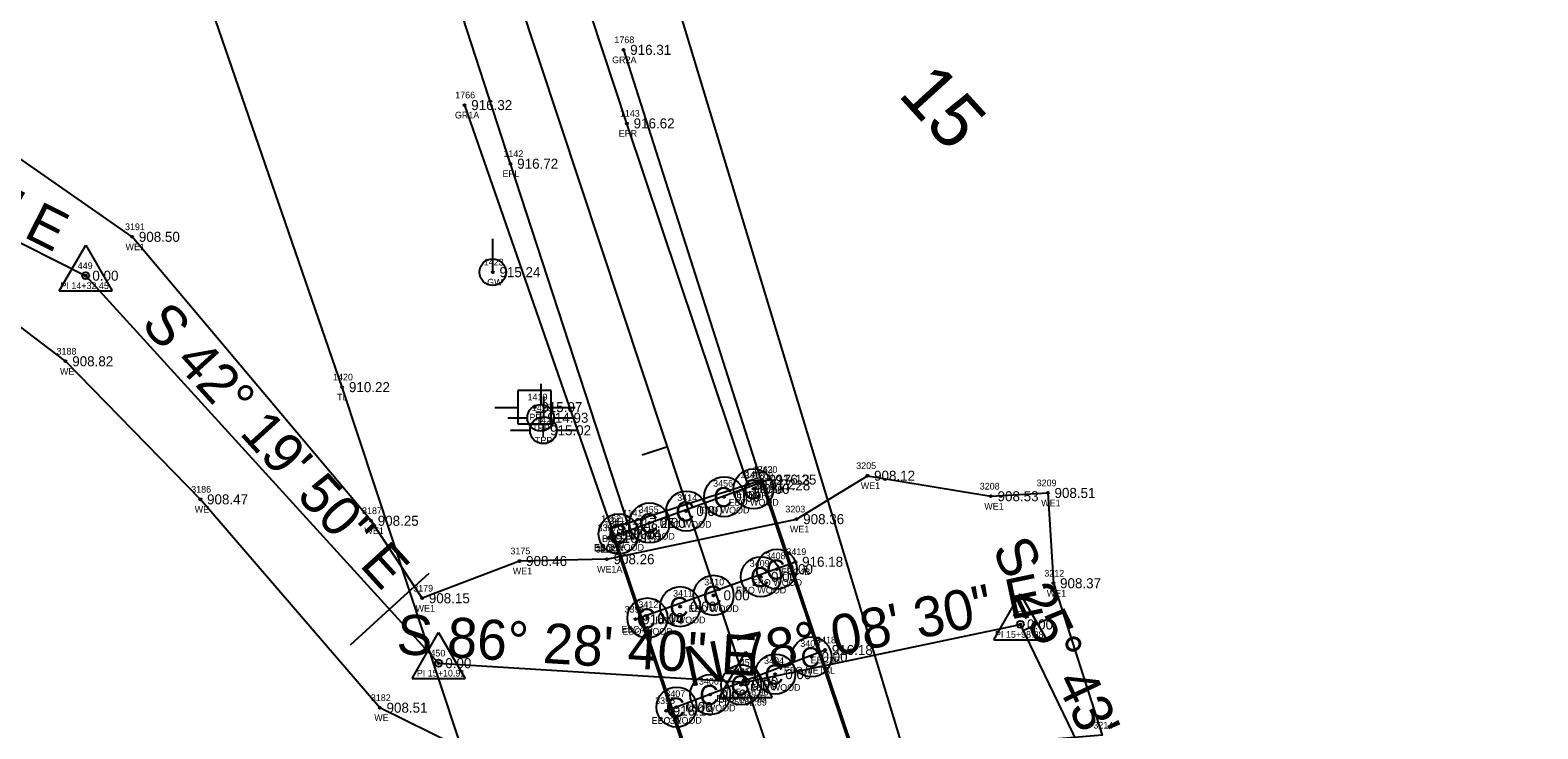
# Model space of a CAD drawing. Extents: x 1528109 to 1531398, y 1157799 to 1162548.
# Drawn here: x 1529420.7 to 1529646.4, y 1160628.8 to 1160733.4 of the extents above; entities that cross this region are included whole.
import ezdxf

# ---------------------------------------------------------------- set-up
doc = ezdxf.new("R2010")
doc.units = 0
for name, color, linetype in [('RD_EX_Bridge', 7, 'Continuous'), ('RD_EX_Bridge_txCode', 7, 'Continuous'), ('RD_EX_GuardRail', 7, 'Continuous'), ('RD_EX_GuardRail_txCode', 7, 'Continuous'), ('RD_EX_H2O', 7, 'Continuous'), ('RD_EX_H2O_txCode', 7, 'Continuous'), ('RD_EX_Road', 7, 'Continuous'), ('RD_EX_Road_txCode', 7, 'Continuous'), ('RD_EX_TX_Bridge_ELEV', 7, 'Continuous'), ('RD_EX_TX_GuardRail_ELEV', 7, 'Continuous'), ('RD_EX_TX_H2O_ELEV', 7, 'Continuous'), ('RD_EX_TX_Road_ELEV', 7, 'Continuous'), ('RD_EX_TX_UT_ELEV', 7, 'Continuous'), ('RD_EX_TX_VEG_ELEV', 7, 'Continuous'), ('RD_EX_UT', 7, 'Continuous'), ('RD_EX_UT_txCode', 7, 'Continuous'), ('RD_EX_VEG', 7, 'Continuous'), ('RD_EX_VEG_txCode', 7, 'Continuous'), ('RD_HC_Cl', 7, 'Continuous'), ('RD_HC_Data', 7, 'Continuous'), ('RD_HC_Data_Tic', 7, 'Continuous'), ('RD_HC_Survey_ELEV', 7, 'Continuous'), ('RD_HC_TX_Sta50', 7, 'Continuous'), ('RD_HC_txCode', 7, 'Continuous'), ('RD_SMD_Locator', 7, 'Continuous')]:
    doc.layers.add(name, color=color, linetype=linetype)

msp = doc.modelspace()

# ---------------------------------------------------------------- linework, layer by layer
at = {"layer": 'RD_EX_Bridge'}
for p, q in [((1529507.33, 1160657.36), (1529531.31, 1160666.08)), ((1529511.38, 1160645.17), (1529535.31, 1160653.78)), ((1529515.94, 1160631.48), (1529539.75, 1160640.57))]:
    msp.add_line(p, q, dxfattribs=at)
msp.add_lwpolyline([(1529525.42, 1160605.53), (1529507.61, 1160658.74), (1529530.31, 1160666.05), (1529548.07, 1160613.22), (1529525.42, 1160605.53)], dxfattribs=at)
for centre in [(1529529.03, 1160664.68), (1529524.64, 1160663.51), (1529513.48, 1160659.6), (1529518.97, 1160661.37), (1529508.85, 1160657.95), (1529530.14, 1160651.53), (1529532.52, 1160652.67), (1529523.05, 1160648.75), (1529518.05, 1160647.06), (1529513.15, 1160645.36), (1529537.71, 1160639.54), (1529532.29, 1160636.96), (1529527.19, 1160635.34), (1529522.55, 1160633.89), (1529517.51, 1160632.03)]:
    msp.add_circle(centre, 3, dxfattribs=at)
at = {"layer": 'RD_EX_GuardRail'}
for points in [[(1529509.58, 1160730.41), (1529530.39, 1160665.21), (1529547.6, 1160613.9), (1529568.73, 1160551.39)], [(1529485.78, 1160722.14), (1529508.08, 1160657.89), (1529525.55, 1160605.96), (1529546.28, 1160543.06)]]:
    msp.add_lwpolyline(points, dxfattribs=at)
at = {"layer": 'RD_EX_H2O'}
for points in [[(1529507.08, 1160654.16), (1529493.99, 1160653.89), (1529479.43, 1160648.32), (1529471.78, 1160659.91), (1529436.02, 1160702.42), (1529412.59, 1160718.71), (1529383.74, 1160723.99), (1529372.31, 1160730.96)], [(1529521, 1160615.38), (1529503.83, 1160616.75), (1529473.1, 1160631.93), (1529446.23, 1160663.12), (1529426.05, 1160683.79), (1529383.42, 1160716.17), (1529369.51, 1160721.6)], [(1529507.08, 1160654.16), (1529535.47, 1160660.16), (1529546.08, 1160666.66), (1529564.57, 1160663.59), (1529573.09, 1160664.08), (1529573.92, 1160650.56), (1529581.25, 1160627.81), (1529566.4, 1160626.59), (1529547.24, 1160619.32), (1529521, 1160615.38)]]:
    msp.add_lwpolyline(points, dxfattribs=at)
at = {"layer": 'RD_EX_Road'}
for points in [[(1529528.19, 1160665.37), (1529510.09, 1160719.4), (1529492.11, 1160773.83), (1529472.86, 1160831.89), (1529455.25, 1160885.7), (1529433.06, 1160953.02), (1529413.26, 1161012.66), (1529395.22, 1161066.33), (1529377.86, 1161117.62), (1529363.16, 1161161.33), (1529348.16, 1161206.56), (1529333.57, 1161252.24), (1529320.05, 1161297.19), (1529307.5, 1161343.12), (1529295.36, 1161392.47), (1529283.79, 1161439.12), (1529272.62, 1161487.93), (1529262.64, 1161533.9), (1529252.45, 1161583.34), (1529240.63, 1161641.16), (1529229.5, 1161693.86), (1529218.57, 1161746.16)], [(1529510.2, 1160659.58), (1529492.66, 1160713.36), (1529475.03, 1160767.61), (1529455.71, 1160825.55), (1529437.49, 1160880.26), (1529415.33, 1160947.23), (1529395.75, 1161006.55), (1529377.65, 1161060.34), (1529360.29, 1161111.94), (1529345.55, 1161156.09), (1529330.61, 1161201.56), (1529315.83, 1161247.44), (1529302.44, 1161292.45), (1529289.17, 1161338.91), (1529275.89, 1161388.06), (1529264.25, 1161434.63), (1529253.41, 1161483.36), (1529243.45, 1161529.92), (1529233.03, 1161578.98), (1529220.82, 1161638.04), (1529209.58, 1161691.45), (1529199.11, 1161741.7)]]:
    msp.add_lwpolyline(points, dxfattribs=at)
at = {"layer": 'RD_EX_UT'}
for p, q in [((1529490, 1160697.13), (1529490, 1160702.13)), ((1529498.76, 1160679.44), (1529493.76, 1160679.44)), ((1529493.76, 1160679.44), (1529493.76, 1160674.44)), ((1529497.18, 1160680.4), (1529497.18, 1160677.33)), ((1529497.58, 1160678.53), (1529497.58, 1160675.46)), ((1529498.76, 1160674.44), (1529498.76, 1160679.44)), ((1529490.33, 1160676.88), (1529493.8, 1160676.88)), ((1529498.69, 1160676.88), (1529502.33, 1160676.88)), ((1529492.25, 1160675.34), (1529495.18, 1160675.34)), ((1529493.76, 1160674.44), (1529498.76, 1160674.44)), ((1529499.18, 1160675.34), (1529502.25, 1160675.34)), ((1529492.65, 1160673.48), (1529495.58, 1160673.48)), ((1529499.58, 1160673.48), (1529502.65, 1160673.48))]:
    msp.add_line(p, q, dxfattribs=at)
for centre in [(1529490, 1160697.13), (1529497.18, 1160675.33), (1529497.58, 1160673.46)]:
    msp.add_circle(centre, 2, dxfattribs=at)
at = {"layer": 'RD_EX_VEG'}
for points in [[(1529712.92, 1160313.49), (1529665.06, 1160326.09), (1529626.42, 1160407.72), (1529580.03, 1160531.48), (1529510.74, 1160760.21), (1529455.97, 1160902.21), (1529420.7, 1161006.64), (1529376.36, 1161143.49), (1529336.53, 1161275.85), (1529306.04, 1161391.66)], [(1529543.38, 1160321.88), (1529583.48, 1160329.53), (1529467.47, 1160679.92), (1529425.09, 1160802.81), (1529349.9, 1161010.59), (1529312.85, 1161137.15)]]:
    msp.add_lwpolyline(points, dxfattribs=at)
at = {"layer": 'RD_HC_Cl'}
for p, q in [((1529527.85, 1160635.77), (1529346.24, 1161183.48)), ((1529370.26, 1160726.25), (1529429.06, 1160696.6)), ((1529429.06, 1160696.6), (1529481.89, 1160638.6)), ((1529527.85, 1160635.77), (1529568.97, 1160644.4)), ((1529568.97, 1160644.4), (1529584.48, 1160612.21)), ((1529481.89, 1160638.6), (1529527.85, 1160635.77)), ((1529913.5, 1159487.74), (1529527.85, 1160635.77))]:
    msp.add_line(p, q, dxfattribs=at)
at = {"layer": 'RD_HC_Data'}
for p, q in [((1529425.09, 1160694.31), (1529429.06, 1160701.19)), ((1529429.06, 1160701.19), (1529433.03, 1160694.31)), ((1529425.09, 1160694.31), (1529433.03, 1160694.31)), ((1529565, 1160642.11), (1529568.97, 1160648.99)), ((1529568.97, 1160648.99), (1529572.94, 1160642.11)), ((1529477.92, 1160636.3), (1529481.9, 1160643.18)), ((1529481.9, 1160643.18), (1529485.86, 1160636.3)), ((1529523.88, 1160633.48), (1529527.86, 1160640.35)), ((1529523.88, 1160633.48), (1529527.86, 1160640.35)), ((1529527.86, 1160640.35), (1529531.82, 1160633.48)), ((1529527.86, 1160640.35), (1529531.82, 1160633.48)), ((1529565, 1160642.11), (1529572.94, 1160642.11)), ((1529477.92, 1160636.3), (1529485.86, 1160636.3)), ((1529523.88, 1160633.48), (1529531.82, 1160633.48)), ((1529523.88, 1160633.48), (1529531.82, 1160633.48))]:
    msp.add_line(p, q, dxfattribs=at)
for centre in [(1529429.06, 1160696.6), (1529568.97, 1160644.4), (1529481.89, 1160638.6), (1529527.85, 1160635.77), (1529527.85, 1160635.77)]:
    msp.add_circle(centre, 0.529, dxfattribs=at)
at = {"layer": 'RD_HC_Data_Tic'}
for p, q in [((1529516.17, 1160670.99), (1529512.38, 1160669.73)), ((1529474.55, 1160646.66), (1529480.46, 1160652.05)), ((1529474.55, 1160646.66), (1529468.63, 1160641.28)), ((1529569.42, 1160643.48), (1529573.02, 1160645.21))]:
    msp.add_line(p, q, dxfattribs=at)
at = {"layer": 'RD_SMD_Locator'}
for centre in [(1529509.58, 1160730.41), (1529485.78, 1160722.14), (1529510.09, 1160719.4), (1529492.66, 1160713.36), (1529436.02, 1160702.42), (1529429.06, 1160696.6), (1529490, 1160697.13), (1529426.05, 1160683.79), (1529467.47, 1160679.92), (1529496.27, 1160676.93), (1529497.18, 1160675.33), (1529497.58, 1160673.46), (1529528.19, 1160665.37), (1529529.03, 1160664.68), (1529530.31, 1160666.05), (1529530.39, 1160665.21), (1529531.31, 1160666.08), (1529546.08, 1160666.66), (1529446.23, 1160663.12), (1529524.64, 1160663.51), (1529564.57, 1160663.59), (1529573.09, 1160664.08), (1529518.97, 1160661.37), (1529535.47, 1160660.16), (1529471.78, 1160659.91), (1529507.61, 1160658.74), (1529508.08, 1160657.89), (1529508.85, 1160657.95), (1529510.2, 1160659.58), (1529513.48, 1160659.6), (1529507.33, 1160657.36), (1529493.99, 1160653.89), (1529507.08, 1160654.16), (1529507.08, 1160654.16), (1529535.31, 1160653.78), (1529530.14, 1160651.53), (1529532.52, 1160652.67), (1529523.05, 1160648.75), (1529573.92, 1160650.56), (1529479.43, 1160648.32), (1529518.05, 1160647.06), (1529511.38, 1160645.17), (1529513.15, 1160645.36), (1529568.97, 1160644.4), (1529539.75, 1160640.57), (1529481.89, 1160638.6), (1529537.71, 1160639.54), (1529527.19, 1160635.34), (1529527.85, 1160635.77), (1529527.85, 1160635.77), (1529532.29, 1160636.96), (1529522.55, 1160633.89), (1529473.1, 1160631.93), (1529515.94, 1160631.48), (1529517.51, 1160632.03)]:
    msp.add_circle(centre, 0.15, dxfattribs=at)

# ---------------------------------------------------------------- texts
at = {"layer": 'RD_EX_Bridge'}
for p in [(1529523.01, 1160661.95), (1529527.4, 1160663.12), (1529517.33, 1160659.81), (1529511.85, 1160658.04), (1529507.22, 1160656.39), (1529530.89, 1160651.11), (1529528.51, 1160649.97), (1529521.42, 1160647.19), (1529511.52, 1160643.8), (1529516.42, 1160645.5), (1529536.08, 1160637.98), (1529530.66, 1160635.39), (1529520.92, 1160632.33), (1529525.56, 1160633.78), (1529515.88, 1160630.46)]:
    msp.add_text('C', height=3, dxfattribs=at).set_placement(p)
at = {"layer": 'RD_EX_Bridge_txCode'}
for s, p in [('3413', (1529527.68, 1160666.18)), ('1763', (1529528.94, 1160667.05)), ('3420', (1529529.64, 1160667.08)), ('3456', (1529522.99, 1160665.01)), ('BRC', (1529529.06, 1160664.05)), ('EBC5B', (1529529.16, 1160664.08)), ('3414', (1529517.62, 1160662.87)), ('EBO WOOD', (1529525.31, 1160662.18)), ('1762', (1529506.24, 1160659.74)), ('3415', (1529507.51, 1160659.45)), ('3455', (1529511.85, 1160661.1)), ('EBO WOOD', (1529520.92, 1160661.01)), ('3397', (1529505.7, 1160658.36)), ('EBO WOOD', (1529509.76, 1160657.1)), ('EBO WOOD', (1529515.25, 1160658.87)), ('EBO WOOD', (1529505.14, 1160655.45)), ('EBC5A', (1529505.17, 1160655.36)), ('BRC', (1529506.36, 1160656.74)), ('3419', (1529533.96, 1160654.78)), ('3409', (1529528.47, 1160653.03)), ('3408', (1529530.85, 1160654.17)), ('3410', (1529521.66, 1160650.25)), ('EBO WOOD', (1529528.8, 1160650.17)), ('EBC4B', (1529533.16, 1160651.78)), ('3411', (1529516.99, 1160648.56)), ('EBO WOOD', (1529526.42, 1160649.03)), ('3396', (1529509.73, 1160646.17)), ('3412', (1529511.8, 1160646.86)), ('EBO WOOD', (1529519.33, 1160646.25)), ('EBO WOOD', (1529514.34, 1160644.56)), ('EBC4A', (1529509.22, 1160643.17)), ('EBO WOOD', (1529509.43, 1160642.86)), ('3418', (1529538.4, 1160641.57)), ('3403', (1529536.04, 1160641.04)), ('3405', (1529525.52, 1160636.84)), ('3404', (1529530.62, 1160638.46)), ('EBO METAL', (1529533.57, 1160637.04)), ('EBC3B', (1529537.6, 1160638.57)), ('3406', (1529520.86, 1160635.39)), ('EBO WOOD', (1529528.57, 1160634.46)), ('3395', (1529514.31, 1160632.48)), ('3407', (1529515.84, 1160633.53)), ('EBO WOOD', (1529523.48, 1160632.84)), ('EBO WOOD', (1529518.84, 1160631.39)), ('EBC3A', (1529513.77, 1160629.48)), ('EBO WOOD', (1529513.79, 1160629.53))]:
    msp.add_text(s, height=1, dxfattribs=at).set_placement(p)
at = {"layer": 'RD_EX_GuardRail_txCode'}
for s, p in [('1768', (1529508.21, 1160731.41)), ('GR2A', (1529507.87, 1160728.41)), ('1766', (1529484.38, 1160723.14)), ('GR1A', (1529484.34, 1160720.14)), ('1769', (1529529.02, 1160666.21)), ('GR2', (1529529.16, 1160663.21)), ('1767', (1529506.71, 1160658.89)), ('GR1', (1529507.13, 1160655.89))]:
    msp.add_text(s, height=1, dxfattribs=at).set_placement(p)
at = {"layer": 'RD_EX_H2O_txCode'}
for s, p in [('3191', (1529434.95, 1160703.42)), ('WE1', (1529435.03, 1160700.42)), ('3188', (1529424.7, 1160684.79)), ('WE', (1529425.21, 1160681.79)), ('3205', (1529544.41, 1160667.66)), ('3186', (1529444.86, 1160664.12)), ('WE1', (1529545.09, 1160664.66)), ('3208', (1529562.9, 1160664.59)), ('3209', (1529571.42, 1160665.08)), ('WE1', (1529563.58, 1160661.59)), ('WE1', (1529572.1, 1160662.08)), ('WE', (1529445.39, 1160661.12)), ('3187', (1529470.43, 1160660.91)), ('3203', (1529533.8, 1160661.16)), ('WE1', (1529470.79, 1160657.91)), ('WE1', (1529534.48, 1160658.16)), ('3175', (1529492.64, 1160654.89)), ('3202', (1529505.41, 1160655.16)), ('3171', (1529506.02, 1160655.16)), ('WE1', (1529493, 1160651.89)), ('WE1A', (1529505.61, 1160652.16)), ('WE1A', (1529505.61, 1160652.16)), ('3212', (1529572.57, 1160651.56)), ('3179', (1529478.09, 1160649.32)), ('WE1', (1529572.94, 1160648.56)), ('WE1', (1529478.45, 1160646.32)), ('3182', (1529471.75, 1160632.93)), ('WE', (1529472.26, 1160629.93)), ('3214', (1529579.91, 1160628.81))]:
    msp.add_text(s, height=1, dxfattribs=at).set_placement(p)
at = {"layer": 'RD_EX_Road_txCode'}
for s, p in [('1143', (1529509.03, 1160720.4)), ('EPR', (1529508.86, 1160717.4)), ('1142', (1529491.6, 1160714.36)), ('EPL', (1529491.45, 1160711.36)), ('1140', (1529527.08, 1160666.37)), ('EPRA', (1529526.47, 1160663.37)), ('1141', (1529509.42, 1160660.58)), ('EPLA', (1529508.51, 1160657.58))]:
    msp.add_text(s, height=1, dxfattribs=at).set_placement(p)
at = {"layer": 'RD_EX_TX_Bridge_ELEV'}
for s, p in [('0.00', (1529530.53, 1160663.93)), ('917.13', (1529531.31, 1160665.3)), ('916.25', (1529532.31, 1160665.33)), ('0.00', (1529526.14, 1160662.76)), ('0.00', (1529514.98, 1160658.85)), ('0.00', (1529520.47, 1160660.62)), ('916.13', (1529508.33, 1160656.61)), ('917.08', (1529508.61, 1160657.99)), ('0.00', (1529510.35, 1160657.2)), ('0.00', (1529534.02, 1160651.92)), ('916.18', (1529536.31, 1160653.03)), ('0.00', (1529531.64, 1160650.78)), ('0.00', (1529524.55, 1160648)), ('0.00', (1529519.55, 1160646.31)), ('916.14', (1529512.38, 1160644.42)), ('0.00', (1529514.65, 1160644.61)), ('0.00', (1529539.21, 1160638.79)), ('916.18', (1529540.75, 1160639.82)), ('0.00', (1529533.79, 1160636.21)), ('0.00', (1529528.69, 1160634.59)), ('0.00', (1529524.05, 1160633.14)), ('916.13', (1529516.94, 1160630.73)), ('0.00', (1529519.01, 1160631.28))]:
    msp.add_text(s, height=1.5, dxfattribs=at).set_placement(p)
at = {"layer": 'RD_EX_TX_GuardRail_ELEV'}
for s, p in [('916.31', (1529510.58, 1160729.66)), ('916.32', (1529486.78, 1160721.39)), ('917.28', (1529531.39, 1160664.46)), ('917.14', (1529509.08, 1160657.14))]:
    msp.add_text(s, height=1.5, dxfattribs=at).set_placement(p)
at = {"layer": 'RD_EX_TX_H2O_ELEV'}
for s, p in [('908.50', (1529437.02, 1160701.67)), ('908.82', (1529427.05, 1160683.04)), ('908.12', (1529547.08, 1160665.91)), ('908.51', (1529574.09, 1160663.33)), ('908.47', (1529447.23, 1160662.37)), ('908.53', (1529565.57, 1160662.84)), ('908.25', (1529472.78, 1160659.16)), ('908.36', (1529536.47, 1160659.41)), ('908.46', (1529494.99, 1160653.14)), ('908.26', (1529508.08, 1160653.41)), ('908.26', (1529508.08, 1160653.41)), ('908.37', (1529574.92, 1160649.81)), ('908.15', (1529480.43, 1160647.57)), ('908.51', (1529474.1, 1160631.18))]:
    msp.add_text(s, height=1.5, dxfattribs=at).set_placement(p)
at = {"layer": 'RD_EX_TX_Road_ELEV'}
for s, p in [('916.62', (1529511.09, 1160718.65)), ('916.72', (1529493.66, 1160712.61)), ('917.22', (1529529.19, 1160664.62)), ('917.25', (1529511.2, 1160658.83))]:
    msp.add_text(s, height=1.5, dxfattribs=at).set_placement(p)
at = {"layer": 'RD_EX_TX_UT_ELEV'}
for s, p in [('915.24', (1529491, 1160696.38)), ('914.93', (1529498.18, 1160674.58)), ('915.02', (1529498.58, 1160672.71))]:
    msp.add_text(s, height=1.5, dxfattribs=at).set_placement(p)
at = {"layer": 'RD_EX_TX_VEG_ELEV'}
msp.add_text('910.22', height=1.5, dxfattribs=at).set_placement((1529468.47, 1160679.17))
at = {"layer": 'RD_EX_UT'}
for p in [(1529496.34, 1160674.28), (1529496.73, 1160672.41)]:
    msp.add_text('T', height=2, dxfattribs=at).set_placement(p)
at = {"layer": 'RD_EX_UT_txCode'}
for s, p in [('1423', (1529488.65, 1160698.13)), ('GW', (1529489.16, 1160695.13)), ('1419', (1529495.21, 1160677.93)), ('1422', (1529495.84, 1160676.33)), ('PP', (1529495.49, 1160674.93)), ('TPP', (1529495.92, 1160673.33)), ('1421', (1529496.51, 1160674.46)), ('TPP', (1529496.31, 1160671.46))]:
    msp.add_text(s, height=1, dxfattribs=at).set_placement(p)
at = {"layer": 'RD_EX_VEG_txCode'}
for s, p in [('1420', (1529466.09, 1160680.92)), ('TL', (1529466.7, 1160677.92))]:
    msp.add_text(s, height=1, dxfattribs=at).set_placement(p)
at = {"layer": 'RD_HC_Data'}
for s, rotation, p in [('S 63%%d 14\' 19" E', 333.2386, (1529376.17, 1160724.39)), ('S 42%%d 19\' 50" E', 312.3307, (1529437.17, 1160689.18)), ('S 25%%d 43\' 27" E', 295.7242, (1529564.66, 1160655.66)), ('N 78%%d 08\' 30" E', 11.8583, (1529519.43, 1160635.02)), ('S 86%%d 28\' 40" E', 356.4777, (1529475.49, 1160639.99))]:
    msp.add_text(s, height=6, rotation=rotation, dxfattribs=at).set_placement(p)
at = {"layer": 'RD_HC_Survey_ELEV'}
for s, p in [('0.00', (1529430.06, 1160695.85)), ('915.07', (1529497.27, 1160676.18)), ('0.00', (1529569.97, 1160643.65)), ('0.00', (1529482.89, 1160637.85)), ('0.00', (1529528.85, 1160635.02)), ('0.00', (1529528.85, 1160635.02))]:
    msp.add_text(s, height=1.5, dxfattribs=at).set_placement(p)
at = {"layer": 'RD_HC_TX_Sta50'}
msp.add_text('15', height=8, rotation=312.3307, dxfattribs=at).set_placement((1529550.51, 1160723.65))
at = {"layer": 'RD_HC_txCode'}
for s, p in [('449', (1529427.87, 1160697.6)), ('PI 14+32.45', (1529425.28, 1160694.6)), ('452', (1529567.79, 1160645.4)), ('PI 15+98.98', (1529565.19, 1160642.4)), ('450', (1529480.67, 1160639.6)), ('451', (1529526.96, 1160638.2)), ('419', (1529526.96, 1160636.77)), ('PI 15+10.91', (1529478.64, 1160636.6)), ('PI 35+62.89', (1529523.77, 1160632.26)), ('PI 15+56.96', (1529524.03, 1160633.77))]:
    msp.add_text(s, height=1, dxfattribs=at).set_placement(p)

doc.saveas('drawing.dxf')
